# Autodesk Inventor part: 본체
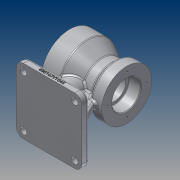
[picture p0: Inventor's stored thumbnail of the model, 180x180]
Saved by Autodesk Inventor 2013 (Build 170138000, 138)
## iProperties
Created: 2019-01
Part Number: 본체
Material: 알루미늄 6061
Document SubType Name: Modeling
Designer: Administrator
Mass: 902.157 g
Surface Area: 600.918 cm^2
Volume: 332.899 cm^3
Density: 2.71 g/cm^3
Author: Administrator
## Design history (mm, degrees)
sketch "스케치1"
  geometry: L1 (-40, 0)-(40, 0); L2 (-40, 0)-(-40, 40); L3 (-40, 40)-(-15, 40); L4 (-15, 40)-(5.785, 28); L5 (25, 35)-(40, 35); L6 (40, 35)-(40, 0); L7 (5.785, 28)-(19.126, 28); L8 (25, 35)-(19.126, 28); 2 further points
  constraints: 16 end point, 3 perpendicular, 2 parallel, 1 coincident, 1 horizontal, 1 midpoint
  dimensions: "d0" = 80 distance of L1.start L1.end; "d2" = 25 distance of L2.end L3.end; "d3" = 15 distance of L5.start L5.end; "d5" = 30 deg angle of L7 L4; "d6" = 50 deg angle of L7 L8; "d7" = 70 diameter of L5 L1; "d8" = 80 diameter of L3 L1; "d9" = 56 diameter of L7 L1
revolve "회전1" sketch "스케치1" stored, may be unused: angle "d10" = 90 deg
node "작업 평면1"
sketch "스케치2"
  geometry: L1 (40, 40)-(40, -40) reference; L2 (-57, 46)-(35, 46); L3 (35, 46)-(35, -46); L4 (35, -46)-(-57, -46); L5 (-57, -46)-(-57, 46); L6 (-57, 46)-(35, -46); L7 (35, 46)-(-57, -46); 3 further points
  constraints: 12 end point, 4 midpoint, 2 parallel, 1 horizontal, 1 horizontal alignment, 1 perpendicular
  dimensions: "d12" = 92 distance of L3.end L4.end; "d14" = 92 distance of L4.end L2.start; "d15" = 5 distance between parallel lines of L3 L1
extrude "돌출1" join sketch "스케치2" distance "d16" = 10; taper "d17" = 0 deg
sketch "스케치3"
  geometry: L1 (-35, -46)-(-35, 46) reference; L2 (57, 46)-(57, -46) reference; C1 r 16 at (-5, 0); 1 further point
  constraints: 1 centre point, 1 horizontal alignment
  dimensions: "d18" = 32 diameter of C1; "d20" = 30 distance from line of L1 C1.centre
extrude "돌출2" join sketch "스케치3" stored distance "d24" = 10; taper "d25" = 0 deg
sketch "스케치4"
  geometry: L1 (-15, 40)-(5.785, 28) reference; L2 (5.785, 28)-(19.126, 28) reference; L3 (19.126, 28)-(25, 35) reference; L4 (25, 35)-(40, 35) reference; L5 (40, 35)-(40, -35) reference; L6 (40, -35)-(25, -35) reference; L7 (25, -35)-(19.126, -28) reference; L8 (19.126, -28)-(11, -28) reference; L9 (11, -28)-(11, -70) reference; L10 (11, -70)-(57, -70) reference; L11 (57, -70)-(57, -80) reference; L12 (57, -80)-(-35, -80) reference; L13 (-35, -80)-(-35, -70) reference; L14 (-35, -70)-(-21, -70) reference; L15 (-21, -70)-(-21, -40) reference; L16 (-21, -40)-(-40, -40) reference; L17 (-40, -40)-(-40, 40) reference; L18 (-40, 40)-(-15, 40) reference; L19 (47, -70)-(30.679, -35); 1 further point
  constraints: 2 end point, 2 point on line
  dimensions: "d31" = 10 distance of L10.end L19.start; "d32" = 25 deg angle of L19 L11
feature "리브1" sketch "스케치4" dims "d33" = 1, "d34" = 10, "d35" = 0, "d36" = 0, "d37" = 1, "d38" = 1
sketch "스케치5"
  geometry: L1 (-21, -70)-(-21, -40) reference; L2 (-21, -40)-(-40, -40) reference; L3 (-40, -40)-(-40, 40) reference; L4 (-40, 40)-(-15, 40) reference; L5 (-15, 40)-(5.785, 28) reference; L6 (5.785, 28)-(19.126, 28) reference; L7 (19.126, 28)-(25, 35) reference; L8 (25, 35)-(40, 35) reference; L9 (40, 35)-(40, -35) reference; L10 (40, -35)-(30.679, -35) reference; L11 (30.679, -35)-(47, -70) reference; L12 (47, -70)-(57, -70) reference; L13 (57, -70)-(57, -80) reference; L14 (57, -80)-(-35, -80) reference; L15 (-35, -80)-(-35, -70) reference; L16 (-35, -70)-(-21, -70) reference; L17 (-40, 0)-(40, 0); L18 (-40, 0)-(-40, 26); L19 (-40, 26)-(-20, 26); L20 (-20, 26)-(-20, 16); L21 (-20, 16)-(23, 16); L22 (23, 16)-(23, 20); L23 (23, 20)-(40, 20); L24 (40, 20)-(40, 0); 1 further point
  constraints: 16 end point, 3 perpendicular, 2 midpoint, 2 parallel, 2 point on line, 1 collinear
  dimensions: "d39" = 20 distance of L18.end L19.end; "d41" = 17 distance of L22.end L23.end; "d42" = 52 diameter of L19 L17; "d43" = 32 diameter of L21 L17; "d44" = 40 diameter of L23 L17
revolve "회전2" sketch "스케치5" stored, may be unused: angle "d45" = 90 deg
fillet "모깎기1" dims "d46" = 10
sketch "스케치6"
  geometry: L1 (47, -46)-(-25, -46) reference; L2 (-35, -36)-(-35, 36) reference; L3 (-25, 46)-(47, 46) reference; L4 (57, 36)-(57, -36) reference; L5 (47, -5)-(10.199, -5) reference; L6 (10.199, 5)-(47, 5) reference; L7 (47, 5)-(47, -5) reference; C1 r 4.5 at (-25, 36); C2 r 4.5 at (47, 36); C3 r 4.5 at (47, -36); C4 r 4.5 at (-25, -36); A1 r 10 centre (47, -36) between (47, -46) and (57, -36) reference; A2 r 10 centre (-25, -36) between (-35, -36) and (-25, -46) reference; A3 r 10 centre (-25, 36) between (-25, 46) and (-35, 36) reference; A4 r 10 centre (47, 36) between (57, 36) and (47, 46) reference; A5 r 16 centre (-5, 0) between (10.199, 5) and (10.199, -5) reference; 1 further point
  constraints: 4 centre point, 4 coincident
  dimensions: "d47" = 9 diameter of C1; "d48" = 9 diameter of C2; "d49" = 9 diameter of C3; "d50" = 9 diameter of C4
extrude "돌출3" cut sketch "스케치6" stored distance "d51" = 10; taper "d52" = 0 deg
sketch "스케치7" dims "d53" = 66
  geometry: L1 (0, 0)-(0, 33); 2 further points
  constraints: 2 coincident, 2 end point, 1 vertical, 1 vertical alignment, 2 other
hole "구멍1" sketch "스케치7" at (0, 33) diameter "d54" = 3.242; stored, may be unused: countersink angle "d58" = 90 deg, drill point angle "d60" = 118 deg; dims "d55" = 9, "d56" = 4, "d57" = 2, "d59" = 11
sketch "스케치8" dims "d64" = 55
  geometry: L1 (0, 0)-(0, 27.5); 2 further points
  constraints: 2 coincident, 2 end point, 1 vertical, 1 vertical alignment, 2 other
hole "구멍2" sketch "스케치8" at (0, 27.5) diameter "d65" = 3.242; stored, may be unused: countersink angle "d69" = 90 deg, drill point angle "d71" = 118 deg; dims "d66" = 9, "d67" = 4, "d68" = 2, "d70" = 11
node "작업 평면2"
sketch "스케치9"
  geometry: L1 (-35, -70)-(-35, -80) reference; L2 (47, -80)-(-25, -80) reference; 2 further points
  constraints: 1 other
  dimensions: "d76" = 46 distance from line of point (11, -76) L1; "d77" = 4 distance from line of point (11, -76) L2
feature "엠보싱1" sketch "스케치9" dims "d78" = 0.5, "d79" = 0
fillet "모깎기2" dims "d80" = 3
fillet "모깎기3" dims "d81" = 3
fillet "모깎기4" dims "d82" = 3
fillet "모깎기5" dims "d83" = 1
fillet "모깎기6" dims "d84" = 0.6
chamfer "모따기1" distance "d85" = 1; stored, may be unused: second distance "d86" = 2, angle "d87" = 45 deg
fillet "모깎기7" dims "d88" = 3
node "솔리드1"
pattern_circular "원형 패턴1" dims angle "d62" = 360 deg
pattern_circular "원형 패턴2" dims angle "d73" = 360 deg
node "절단 모서리 투영1"
node "절단 모서리 투영2"
node "절단 모서리 투영3"
other parameters: "d75" = 98
